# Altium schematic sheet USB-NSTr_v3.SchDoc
size A4
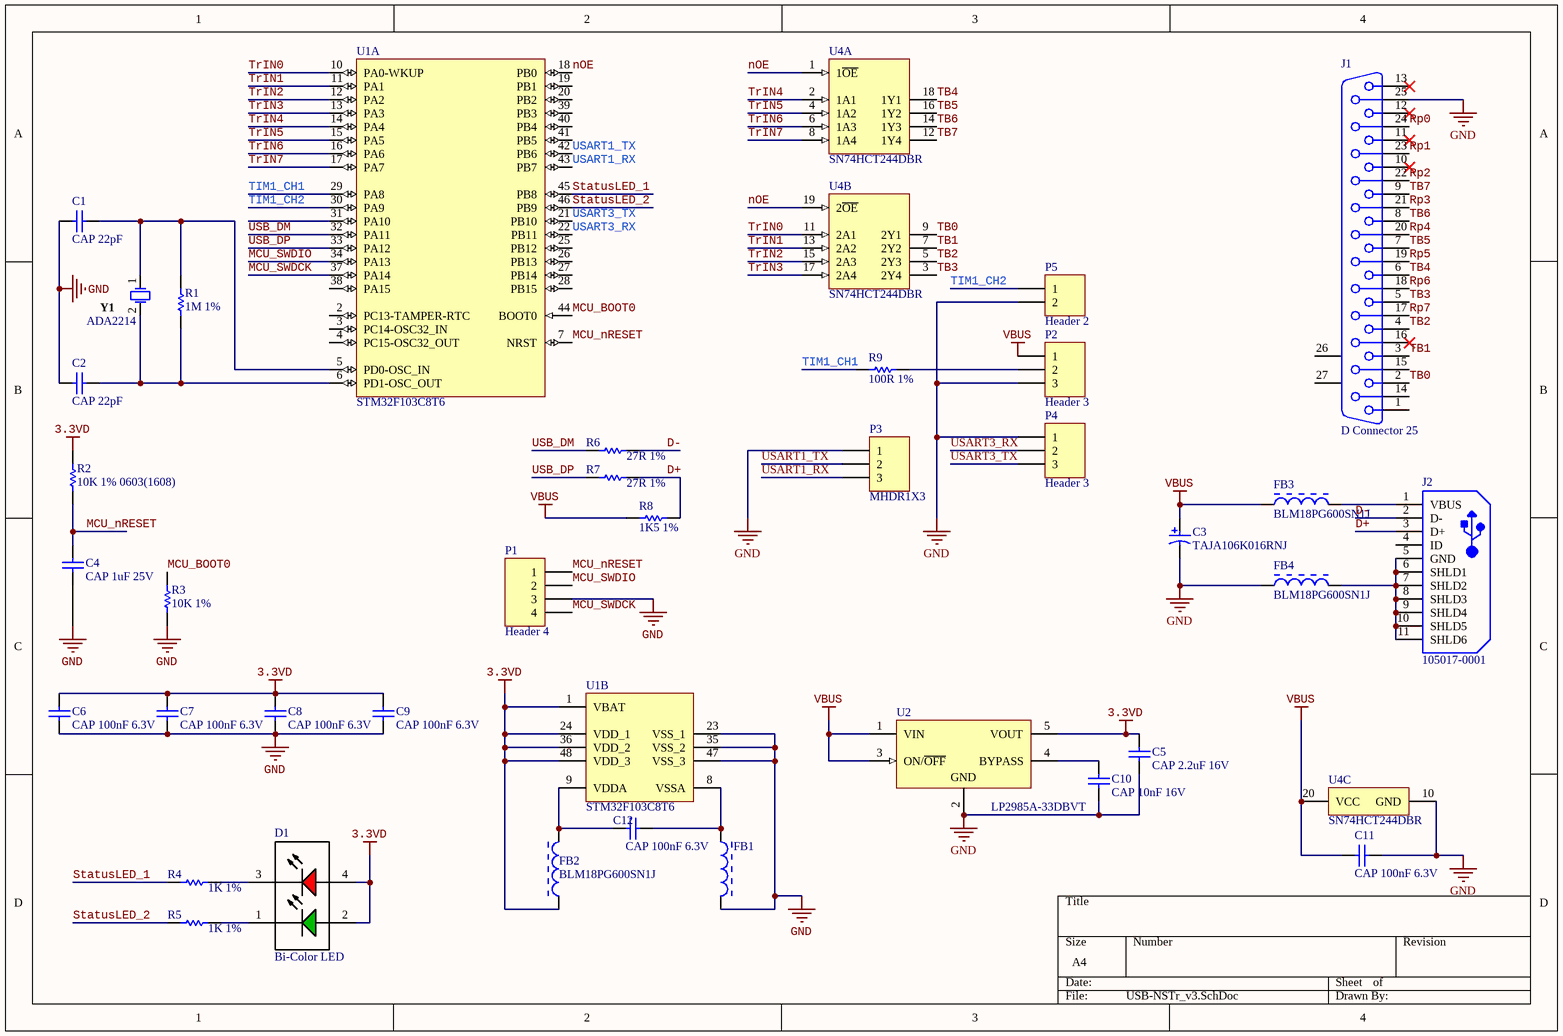
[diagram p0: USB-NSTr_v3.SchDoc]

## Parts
C1  CAP 22pF  [CAPC0603(1608)100_N]
C2  CAP 22pF  [CAPC0603(1608)100_N]
C3  TAJA106K016RNJ  [CAPMP3217X18-T_V]
C4  CAP 1uF 25V  [CAPC0603(1608)100_N]
C5  CAP 2.2uF 16V  [CAPC0603(1608)55_N]
C6  CAP 100nF 6.3V  [CAPC0603(1608)100_N]
C7  CAP 100nF 6.3V  [CAPC0603(1608)100_N]
C8  CAP 100nF 6.3V  [CAPC0603(1608)100_N]
C9  CAP 100nF 6.3V  [CAPC0603(1608)100_N]
C10  CAP 10nF 16V  [CAPC0603(1608)100_N]
C11  CAP 100nF 6.3V  [CAPC0603(1608)100_N]
C12  CAP 100nF 6.3V  [CAPC0603(1608)100_N]
D1  Bi-Color LED  [LED_Bi_Color_1204]
FB1  BLM18PG600SN1J  [MURA-BLM18PG_KG-CHIP-2_V2]  (value not drawn)
FB2  BLM18PG600SN1J  [MURA-BLM18PG_KG-CHIP-2_V2]
FB3  BLM18PG600SN1J  [MURA-BLM18PG_KG-CHIP-2_V2]
FB4  BLM18PG600SN1J  [MURA-BLM18PG_KG-CHIP-2_V2]
J1  D Connector 25  [DB25-EDGE-Female-S]
J2  105017-0001  [USB-MICRO-B_V]
P1  Header 4  [PH2.0-LI-4P]
P2  Header 3  [HDR1X3]
P3  MHDR1X3  [HDR1X3]
P4  Header 3  [HDR1X3]
P5  Header 2  [HDR1X2]
R1  1M 1%  [RESC0603(1608)_N]
R2  10K 1% 0603(1608)  [RESC0603(1608)_N]
R3  10K 1%  [RESC0603(1608)_N]
R4  1K 1%  [RESC0603(1608)_N]
R5  1K 1%  [RESC0603(1608)_N]
R6  27R 1%  [RESC0603(1608)_N]
R7  27R 1%  [RESC0603(1608)_N]
R8  1K5 1%  [RESC0805(2012)_N]
R9  100R 1%  [RESC0603(1608)_N]
U1  STM32F103C8T6  [STM-LQFP48_N]  (parts A,B of 2)
U2  LP2985A-33DBVT  [DBV0005A_N]
U4  SN74HCT244DBR  [DB0020A_N]  (parts A,B,C of 3)
Y1  ADA2214  [ADAI-THHF-49S3]

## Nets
3.3VD: C5.2 C6.2 C7.2 C8.2 C9.2 D1.2(Green-A) D1.4(Red-A) FB2.1 R2.2 U1.1(VBAT) U1.24(VDD_1) U1.36(VDD_2) U1.48(VDD_3) U2.5(VOUT)
GND: C1.2 C2.2 C3.2 C4.1 C5.1 C6.1 C7.1 C8.1 C9.1 C10.1 C11.1 FB1.2 FB4.1 J1.25 P1.3 P2.3 P3.1 P4.1 P5.2 R3.1 U1.23(VSS_1) U1.35(VSS_2) U1.47(VSS_3) U2.2(GND) U4.10(GND)
VBUS: C3.1 C11.2 FB3.1 P2.1 R8.2 U2.1(VIN) U2.3(ON/~{OFF}) U4.20(VCC)
D+: J2.3(D+) R7.2 R8.1
D-: J2.2(D-) R6.2
MCU_BOOT0: R3.2 U1.44(BOOT0)
MCU_nRESET: C4.2 P1.1 R2.1 U1.7(NRST)
MCU_SWDCK: P1.4 U1.37(PA14)
MCU_SWDIO: P1.2 U1.34(PA13)
nOE: U1.18(PB0) U4.1(1~{OE}) U4.19(2~{OE})
Rp0: J1.24
Rp1: J1.23
Rp2: J1.22
Rp3: J1.21
Rp4: J1.20
Rp5: J1.19
Rp6: J1.18
Rp7: J1.17
StatusLED_1: R4.1 U1.45(PB8)
StatusLED_2: R5.1 U1.46(PB9)
TB0: J1.2 U4.9(2Y1)
TB1: J1.3 U4.7(2Y2)
TB2: J1.4 U4.5(2Y3)
TB3: J1.5 U4.3(2Y4)
TB4: J1.6 U4.18(1Y1)
TB5: J1.7 U4.16(1Y2)
TB6: J1.8 U4.14(1Y3)
TB7: J1.9 U4.12(1Y4)
TIM1_CH1: R9.1 U1.29(PA8)
TIM1_CH2: P5.1 U1.30(PA9)
TrIN0: U1.10(PA0-WKUP) U4.11(2A1)
TrIN1: U1.11(PA1) U4.13(2A2)
TrIN2: U1.12(PA2) U4.15(2A3)
TrIN3: U1.13(PA3) U4.17(2A4)
TrIN4: U1.14(PA4) U4.2(1A1)
TrIN5: U1.15(PA5) U4.4(1A2)
TrIN6: U1.16(PA6) U4.6(1A3)
TrIN7: U1.17(PA7) U4.8(1A4)
USART1_RX: P3.3 U1.43(PB7)
USART1_TX: P3.2 U1.42(PB6)
USART3_RX: P4.2 U1.22(PB11)
USART3_TX: P4.3 U1.21(PB10)
USB_DM: R6.1 U1.32(PA11)
USB_DP: R7.1 U1.33(PA12)
NetC1_1: C1.1 R1.2 U1.5(PD0-OSC_IN) Y1.1
NetC2_1: C2.1 R1.1 U1.6(PD1-OSC_OUT) Y1.2
NetC10_2: C10.2 U2.4(BYPASS)
NetC12_1: C12.1 FB1.1 U1.8(VSSA)
NetC12_2: C12.2 FB2.2 U1.9(VDDA)
NetD1_1: D1.1(Green-C) R5.2
NetD1_3: D1.3(Red-C) R4.2
NetFB3_2: FB3.2 J2.1(VBUS)
NetFB4_2: FB4.2 J2.5(GND) J2.6(SHLD1) J2.7(SHLD2) J2.8(SHLD3) J2.9(SHLD4) J2.10(SHLD5) J2.11(SHLD6)
NetP2_2: P2.2 R9.2

Not connected (* = marked no-connect by the designer): J1 1 10* 11* 12* 13* 14 15 16* 26(MH1) 27(MH2); J2 4(ID); U1 2(PC13-TAMPER-RTC) 3(PC14-OSC32_IN) 4(PC15-OSC32_OUT) 19(PB1) 20(PB2) 25(PB12) 26(PB13) 27(PB14) 28(PB15) 31(PA10) 38(PA15) 39(PB3) 40(PB4) 41(PB5)

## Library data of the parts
C1 C2 = CMP-1035-00809-1: CAP 22pF 16V ±10% 0603 (1608 Metric) Thickness 1mm SMD; Case-EIA: 0603; Tolerance: Â±10%; Case-Metric: 1608
C3 = CMP-1661-00004-1: Standard Tantalum, 10 uF, +/- 10%, 16 V, -55 to 125 degC, 2-Pin SMD (1206), RoHS, Tape and Reel; Frequency: 300 MHz; Vce Max: 500 mV; hFE Min: 60; Elements: 2; Case\Package: SOT-26; Max Power Dissipation: 300 mW
C4 = CMP-1035-02741-1: CAP 1uF 25V ±20% 0603 (1608 Metric) Thickness 1mm SMD; Tolerance: Â±20%; Case-EIA: 0603; Case-Metric: 1608
C5 = CMP-1035-02764-1: CAP 2.2uF 16V ±20% 0603 (1608 Metric) Thickness 0.55mm SMD; Tolerance: Â±20%; Case-Metric: 1608; Case-EIA: 0603
C6-C9 C11 C12 = CMP-1035-02576-1: CAP 100nF 6.3V ±10% 0603 (1608 Metric) Thickness 1mm SMD; Tolerance: Â±10%; Case-Metric: 1608; Case-EIA: 0603
C10 = CMP-1035-02310-1: CAP 10nF 16V ±5% 0603 (1608 Metric) Thickness 1mm SMD; Case-Metric: 1608; Case-EIA: 0603; Tolerance: Â±5%
D1 = LED-RG-KAAK-4: LED Indicator, Red / Green, 2 V, -40 to 100 degC, 4-Pin SMD, RoHS, Tape and Reel; Manufacturer: Dialight; Forward Voltage: 2.6V; Rad Hardened: No; Reverse Voltage: 5V; Product Length (mm): 4.3mm; Dominant Wave Length: 570/628nm; Forward Current: 30mA; Lens Type: NonDiffused; Shape Type: Circular; Product Depth (mm): 8.8mm; Number of  Elements: 2; Power Dissipation: 100W; Luminous Intensity: 8/6.5mcd; Main Category: ChipLED; DELETED: Compliant; Test Current (It): 20mA; Emitting Color: YellowGreen/Red; Viewing Angle: 40deg; Product Height (mm): 5mm
FB1-FB4 = CMP-0686-00574-2: Chip Ferrite Bead for Power Lines, 60 Ohm, 500 mA, -55 to 125 degC, 1.6 x 0.8 x 0.95 mm SMD, Tape and Reel; Manufacturer: Murata; Impedance (at 100 MHz): 60 Ohm Typ.; Rated Current: 500 mA; DC Resistance: 0.10 Ohm Max.
J1 = D Connector 25: Receptacle Assembly, 25 Position, Right Angle; PackageDocument: U; Positions: 25
J2 = CMP-2000-05827-1: Micro-USB B Receptacle, Right Angle, Bottom Mount, Surface Mount, with Solder Tabs, -30 to 85 degC, 5-Pin USB, RoHS, Tape and Reel; Manufacturer: Molex; Featured Product: Micro-USBConnectorsUSBConnectors; Other Names: WM1399DKR; Package Version: Rev. F, 12/2012; Number of Contacts: 5; Connector Type: USB-microB; Catalog Drawings: 1050170001; 3D Model: 105017-0001.stp; Mating Products: WM17145-ND-CABLEMICROUSBBTOSTDA1.0MWM17147-ND-CABLEMICROUSBBTOSTDA2.0MWM17146-ND-CABLEMICROUSBBTOSTDA1.5M; PCN Assembly/Origin: ResinSupplier21/Oct/2015; Voltage - Max: 30V; Online Catalog: Molex-MicroUSB
P1 = Header 4: Header, 4-Pin
P2 P4 = Header 3: Header, 3-Pin
P3 = MHDR1X3: Header, 3-Pin
P5 = Header 2: Header, 2-Pin
R1 = CMP-1012-00849-1: 1M 0.1W 1% 0603 (1608 Metric)  SMD; Value: 1000000.00 Ohm; Case-EIA: 0603; Case-Metric: 1608
R2 R3 = CMP-1012-00623-1: 10K 0.1W 1% 0603 (1608 Metric)  SMD; Value: 10000.00 Ohm; Case-EIA: 0603; Case-Metric: 1608
R4 R5 = CMP-1012-00510-1: 1K 0.1W 1% 0603 (1608 Metric)  SMD; Case-Metric: 1608; Case-EIA: 0603; Value: 1000.00 Ohm
R6 R7 = CMP-1012-00331-1: 27R 0.1W 1% 0603 (1608 Metric)  SMD; Case-EIA: 0603; Value: 27.00 Ohm; Case-Metric: 1608
R8 = CMP-1013-00528-1: 1K5 0.125W 1% 0805 (2012 Metric)  SMD; Value: 1500.00 Ohm; Case-Metric: 2012; Case-EIA: 0805
R9 = CMP-1012-00397-1: 100R 0.1W 1% 0603 (1608 Metric)  SMD; Value: 100.00 Ohm; Case-EIA: 0603; Case-Metric: 1608
U1 = CMP-0237-00215-3: ARM Cortex-M3 32-bit MCU, 64 KB Flash, 20 KB Internal RAM, 37 I/Os, 48-pin LQFP, -40 to 85 degC, Tray; Supply Voltage(Vcc) min (V): 2; Internal RAM Size (kB): 20; FLASH Size (Prog) (kB): 64; A/D Converter: 2x12-bit (10 Channel); I/Os (High Current): 37; Operating Frequency(F) (Processor speed) (MHz): 72
U2 = CMP-0758-00051-2: Single Output Low Noise LDO, 150 mA, Fixed 3.3 V Output, 1% Tolerance, 2.2 to 16 V Input, Low IQ, 5-Pin SOT-23 (DBV), -40 to 125 degC, Green (RoHS & no Sb/Br), Tape and Reel; Manufacturer: Texas Instruments; Vdo (Typ) (mV): 280; Fixed Output Options (V): 3.3; Output Options: Fixed Output; Accuracy (%): 1; Iout (Max) (A): 0.15; Iq (Typ) (mA): 0.85
U4 = CMP-0440-00427-3: Octal Buffers And Line Drivers With 3-State Outputs, DB0020A, LARGE T&R; Manufacturer: Texas Instruments; tpd @ Nom Voltage(Max)(ns): 32; Rating: Catalog; VCC(Min)(V): 4.5; F @ Nom Voltage(Max)(Mhz): 25; ICC @ Nom Voltage(Max)(mA): 0.08; Output Type: CMOS; VCC(Max)(V): 5.5; Voltage(Nom)(V): 5; Input Type: TTL; Bits(#): 8
Y1 = CMP-1740-00004-1: Crystal, 12 MHz, 18 pF, 30 PPM, -20 to 70 degC, 2-Pin THD, RoHS; Elements: 1; Max Dual Supply Voltage: 15 V; Propagation Delay: 115 ns; Nominal Dual Supply Voltage: 12 V; Case\Package: PDIP; Min Supply Voltage: 3.5 V; Min Dual Supply Voltage: 1.75 V; Nominal Voltage Gain: 106.02 dB; Nominal Supply Current: 7.5 mA; Max Supply Voltage: 30 V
